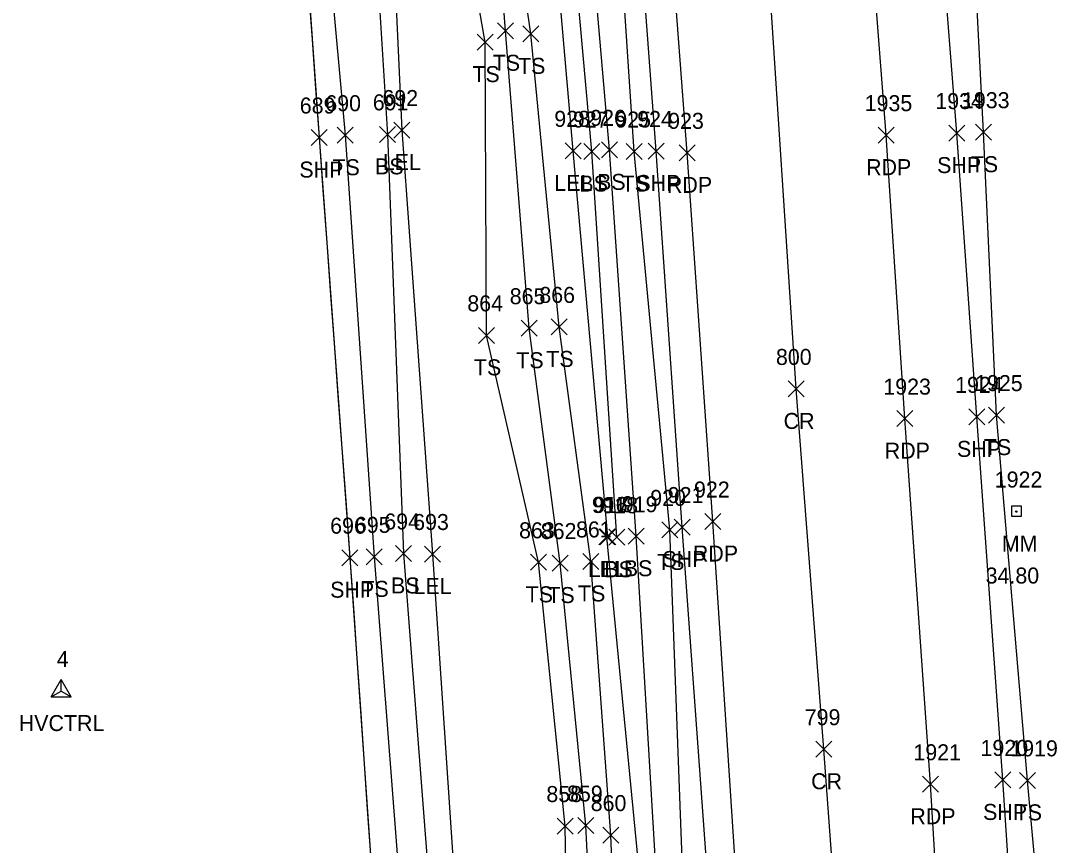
# Model space of a CAD drawing. Extents: x 1650221 to 1650634, y 244606 to 249996.
# Drawn here: x 1650342.9 to 1650471.2, y 245132.2 to 245235.3 of the extents above; entities that cross this region are included whole.
import ezdxf

# ---------------------------------------------------------------- set-up
doc = ezdxf.new("R2010")
doc.units = 0
for name, color, linetype in [('C_A', 7, 'Continuous'), ('C_I', 7, 'Continuous'), ('CPSM', 7, 'Continuous'), ('L_A', 7, 'Continuous'), ('L_I', 7, 'Continuous'), ('L_TIC', 7, 'Continuous'), ('LARO', 7, 'Continuous'), ('LELB', 7, 'Continuous'), ('LSOGP', 7, 'Continuous'), ('P_A', 7, 'Continuous'), ('P_I', 7, 'Continuous'), ('P_TIC', 7, 'Continuous'), ('PET', 7, 'Continuous'), ('PRC', 7, 'Continuous'), ('PSP', 7, 'Continuous'), ('S_A', 7, 'Continuous'), ('S_C', 7, 'Continuous'), ('S_I', 7, 'Continuous'), ('SRM', 7, 'Continuous')]:
    doc.layers.add(name, color=color, linetype=linetype)

msp = doc.modelspace()

# ---------------------------------------------------------------- linework, layer by layer
at = {"layer": 'CPSM'}
for p, q in [((1650346.74, 245150.77), (1650347.99, 245152.93)), ((1650349.24, 245150.77), (1650347.99, 245152.93)), ((1650347.99, 245151.49), (1650347.99, 245152.93)), ((1650346.74, 245150.77), (1650347.99, 245151.49)), ((1650347.99, 245151.49), (1650347.99, 245151.49)), ((1650347.99, 245151.49), (1650349.24, 245150.77)), ((1650346.74, 245150.77), (1650349.24, 245150.77))]:
    msp.add_line(p, q, dxfattribs=at)
at = {"layer": 'L_TIC'}
for points in [[(1650402.51, 245233.02), (1650404.51, 245235.02)], [(1650404.51, 245233.02), (1650402.51, 245235.02)], [(1650405.67, 245232.63), (1650407.67, 245234.63)], [(1650407.67, 245232.63), (1650405.67, 245234.63)], [(1650399.96, 245231.6), (1650401.96, 245233.6)], [(1650401.96, 245231.6), (1650399.96, 245233.6)], [(1650382.48, 245219.96), (1650384.48, 245221.96)], [(1650384.48, 245219.96), (1650382.48, 245221.96)], [(1650387.77, 245220.07), (1650389.77, 245222.07)], [(1650389.77, 245220.07), (1650387.77, 245222.07)], [(1650389.54, 245220.61), (1650391.54, 245222.61)], [(1650391.54, 245220.61), (1650389.54, 245222.61)], [(1650462.25, 245220.34), (1650464.25, 245222.34)], [(1650464.25, 245220.34), (1650462.25, 245222.34)], [(1650410.97, 245218.01), (1650412.97, 245220.01)], [(1650412.97, 245218.01), (1650410.97, 245220.01)], [(1650413.29, 245217.92), (1650415.29, 245219.92)], [(1650415.29, 245217.92), (1650413.29, 245219.92)], [(1650415.52, 245218.13), (1650417.52, 245220.13)], [(1650417.52, 245218.13), (1650415.52, 245220.13)], [(1650418.6, 245217.92), (1650420.6, 245219.92)], [(1650420.6, 245217.92), (1650418.6, 245219.92)], [(1650405.45, 245195.84), (1650407.45, 245197.84)], [(1650407.45, 245195.84), (1650405.45, 245197.84)], [(1650409.2, 245196), (1650411.2, 245198)], [(1650411.2, 245196), (1650409.2, 245198)], [(1650400.15, 245194.95), (1650402.15, 245196.95)], [(1650402.15, 245194.95), (1650400.15, 245196.95)], [(1650463.89, 245184.98), (1650465.89, 245186.98)], [(1650465.89, 245184.98), (1650463.89, 245186.98)], [(1650415.16, 245169.75), (1650417.16, 245171.75)], [(1650417.16, 245169.75), (1650415.16, 245171.75)], [(1650415.29, 245169.75), (1650417.29, 245171.75)], [(1650417.29, 245169.75), (1650415.29, 245171.75)], [(1650416.42, 245169.71), (1650418.42, 245171.71)], [(1650418.42, 245169.71), (1650416.42, 245171.71)], [(1650418.86, 245169.84), (1650420.86, 245171.84)], [(1650420.86, 245169.84), (1650418.86, 245171.84)], [(1650423.05, 245170.63), (1650425.05, 245172.63)], [(1650425.05, 245170.63), (1650423.05, 245172.63)], [(1650386.1, 245167.26), (1650388.1, 245169.26)], [(1650388.1, 245167.26), (1650386.1, 245169.26)], [(1650389.77, 245167.69), (1650391.77, 245169.69)], [(1650391.77, 245167.69), (1650389.77, 245169.69)], [(1650393.38, 245167.62), (1650395.38, 245169.62)], [(1650395.38, 245167.62), (1650393.38, 245169.62)], [(1650406.62, 245166.58), (1650408.62, 245168.58)], [(1650408.62, 245166.58), (1650406.62, 245168.58)], [(1650409.33, 245166.49), (1650411.33, 245168.49)], [(1650411.33, 245166.49), (1650409.33, 245168.49)], [(1650413.16, 245166.69), (1650415.16, 245168.69)], [(1650415.16, 245166.69), (1650413.16, 245168.69)], [(1650467.74, 245139.33), (1650469.74, 245141.33)], [(1650469.74, 245139.33), (1650467.74, 245141.33)], [(1650409.98, 245133.62), (1650411.98, 245135.62)], [(1650411.98, 245133.62), (1650409.98, 245135.62)], [(1650412.57, 245133.68), (1650414.57, 245135.68)], [(1650414.57, 245133.68), (1650412.57, 245135.68)], [(1650415.66, 245132.49), (1650417.66, 245134.49)], [(1650417.66, 245132.49), (1650415.66, 245134.49)]]:
    msp.add_lwpolyline(points, dxfattribs=at)
at = {"layer": 'LARO'}
for points in [[(1650421.38, 244936.36), (1650423.35, 244936.27), (1650425.89, 244936.22), (1650434.3, 244938.37), (1650430.48, 244972), (1650427.02, 245018.52), (1650423.68, 245067.08), (1650420.77, 245123.48), (1650416.16, 245170.75), (1650416.29, 245170.75), (1650411.97, 245219.01), (1650407.36, 245272.17), (1650403.92, 245328.57), (1650398.22, 245379.76), (1650393.14, 245434.28), (1650390.04, 245478.89), (1650387.05, 245523.12), (1650386.02, 245551.2)], [(1650370.23, 245505.43), (1650373.27, 245470.75), (1650376.08, 245419.34), (1650380.61, 245367.82), (1650383.54, 245316.3), (1650388.29, 245270.51), (1650390.54, 245221.61), (1650394.38, 245168.62), (1650397.75, 245118.3), (1650404.08, 245063.51), (1650406.12, 245018.23), (1650409.93, 244966.8), (1650411.89, 244938.28)]]:
    msp.add_lwpolyline(points, dxfattribs=at)
at = {"layer": 'LELB'}
for points in [[(1650349.13, 245703.09), (1650351.39, 245660.59), (1650355.99, 245608.05), (1650358.47, 245560.96), (1650362.91, 245508.7), (1650365.76, 245471.06), (1650369.41, 245419.53), (1650373.04, 245367.18), (1650376.89, 245316.29), (1650379.01, 245269.77), (1650383.48, 245220.96), (1650387.1, 245168.26), (1650390.97, 245118.17), (1650394.99, 245063.19), (1650398.03, 245017.1), (1650401.94, 244967.25), (1650403.81, 244936.86), (1650407.34, 244889.23), (1650410.84, 244834.73), (1650414.52, 244785.95), (1650419.34, 244732.83), (1650422.93, 244682.99), (1650426.36, 244632.18), (1650427.51, 244611.7)], [(1650355.71, 245703.22), (1650358.45, 245660.47), (1650361.92, 245609.02), (1650362.95, 245561.76), (1650366.97, 245508.68), (1650370.97, 245471.38), (1650374.07, 245419.38), (1650376.64, 245367.03), (1650382.18, 245316.08), (1650385.68, 245270.43), (1650388.77, 245221.07), (1650390.77, 245168.69), (1650394.69, 245118), (1650401.29, 245063.19), (1650403.89, 245017.69), (1650406.99, 244966.96), (1650408.31, 244937.61), (1650413.12, 244889.16), (1650416.09, 244835.73), (1650420.51, 244786.1), (1650423.8, 244733.3), (1650426.51, 244682.57), (1650434.12, 244632.73), (1650437.01, 244612.78)], [(1650458.26, 244631.23), (1650456.79, 244671.65), (1650452.78, 244720.4), (1650448.37, 244766.08), (1650444.9, 244801.26), (1650441.62, 244837.94), (1650439.87, 244879.23), (1650437.68, 244923.9), (1650433.87, 244972.21), (1650429.49, 245017.89), (1650426.15, 245066.7), (1650422.69, 245123.12), (1650419.86, 245170.84), (1650416.52, 245219.13), (1650411.95, 245271.56), (1650407.71, 245328.35), (1650401.82, 245379.92), (1650396.45, 245433.97), (1650394.84, 245478.56), (1650392.49, 245522.5), (1650389.35, 245551.29), (1650385.12, 245588.75), (1650380.77, 245632.36), (1650373.15, 245685.41)], [(1650462.3, 244631.92), (1650459.1, 244671.43), (1650455.6, 244720.68), (1650451.8, 244765.92), (1650449.21, 244801.88), (1650446.61, 244838.72), (1650443.38, 244880.99), (1650440.04, 244922.8), (1650437.91, 244972.67), (1650433.82, 245018.12), (1650431.01, 245067.65), (1650425.84, 245123.86), (1650424.05, 245171.63), (1650419.6, 245218.92), (1650416.04, 245272.16), (1650411.76, 245328.09), (1650406.63, 245381.03), (1650402.95, 245434.27), (1650400.25, 245479.81), (1650396.41, 245522.79), (1650395.43, 245551.92), (1650392.44, 245589.61), (1650388.27, 245633.5), (1650384.04, 245685.26)], [(1650471.05, 245115.28), (1650468.74, 245140.33), (1650464.89, 245185.98), (1650463.25, 245221.34), (1650461.37, 245257.85), (1650459.32, 245284.8), (1650456.97, 245315.55), (1650454.6, 245356.59), (1650452.98, 245378.54), (1650450.43, 245426.58), (1650446.12, 245463.42), (1650443.52, 245512.09), (1650441.71, 245548.12), (1650438.37, 245589.38), (1650434.29, 245631.65), (1650429.68, 245683.37)], [(1650417.42, 245170.71), (1650414.29, 245218.92), (1650409.59, 245271.3), (1650405.4, 245327.96), (1650399.15, 245380.06), (1650394.45, 245434.24), (1650392.17, 245479.25), (1650388.55, 245523.47), (1650387.04, 245550.93), (1650374.54, 245599.04)], [(1650411.56, 245100.31), (1650410.98, 245134.62), (1650407.62, 245167.58), (1650401.15, 245195.95), (1650400.96, 245232.6), (1650396.91, 245255.72), (1650396.39, 245280.59), (1650392.18, 245317.33), (1650390.56, 245355.55), (1650386.02, 245389.39), (1650383.37, 245430.51), (1650379.67, 245462.51), (1650379.96, 245467.43), (1650380, 245489.06), (1650377.56, 245510.96), (1650374.72, 245546.33), (1650373.24, 245560.96), (1650373.27, 245589.26)], [(1650417.99, 245100.65), (1650416.66, 245133.49), (1650414.16, 245167.69), (1650410.2, 245197), (1650406.67, 245233.63), (1650402.8, 245260.5), (1650403.69, 245281.19), (1650397.99, 245316.2), (1650398.84, 245356.67), (1650390.42, 245389.46), (1650390.16, 245432.43), (1650385.39, 245460.04), (1650384.98, 245466.18), (1650387.77, 245488.08), (1650384.3, 245517.36), (1650381.95, 245546.8), (1650375.57, 245561.13), (1650373.27, 245589.26)], [(1650438.88, 244749.14), (1650437.59, 244767.7), (1650432.8, 244801.89), (1650429.64, 244835.41), (1650428.64, 244877.68), (1650423.48, 244923.01), (1650423.35, 244936.27), (1650423.08, 244949.37), (1650423.3, 244968.5), (1650419.67, 244981.26), (1650420.71, 245016.76), (1650415.5, 245052.76), (1650413.6, 245072.27), (1650415.28, 245100.97), (1650413.57, 245134.68), (1650410.33, 245167.49), (1650406.45, 245196.84), (1650403.51, 245234.02), (1650401.64, 245258.7)]]:
    msp.add_lwpolyline(points, dxfattribs=at)
at = {"layer": 'LSOGP'}
msp.add_lwpolyline([(1650378.91, 245239.03), (1650379.35, 245232.91), (1650379.78, 245226.79), (1650380.21, 245220.67), (1650380.7, 245214.11), (1650381.18, 245207.54), (1650381.66, 245200.98), (1650382.14, 245194.41), (1650382.62, 245187.85), (1650383.11, 245181.29), (1650383.59, 245174.72), (1650384.07, 245168.16), (1650384.5, 245161.87), (1650384.94, 245155.58), (1650385.37, 245149.29), (1650385.81, 245143.01), (1650386.24, 245136.72), (1650386.67, 245130.43)], dxfattribs=at)
at = {"layer": 'P_TIC'}
for points in [[(1650379.21, 245219.67), (1650381.21, 245221.67)], [(1650381.21, 245219.67), (1650379.21, 245221.67)], [(1650450.1, 245219.97), (1650452.1, 245221.97)], [(1650452.1, 245219.97), (1650450.1, 245221.97)], [(1650458.93, 245220.23), (1650460.93, 245222.23)], [(1650460.93, 245220.23), (1650458.93, 245222.23)], [(1650421.33, 245217.99), (1650423.33, 245219.99)], [(1650423.33, 245217.99), (1650421.33, 245219.99)], [(1650425.2, 245217.76), (1650427.2, 245219.76)], [(1650427.2, 245217.76), (1650425.2, 245219.76)], [(1650438.84, 245188.25), (1650440.84, 245190.25)], [(1650440.84, 245188.25), (1650438.84, 245190.25)], [(1650452.42, 245184.54), (1650454.42, 245186.54)], [(1650454.42, 245184.54), (1650452.42, 245186.54)], [(1650461.4, 245184.76), (1650463.4, 245186.76)], [(1650463.4, 245184.76), (1650461.4, 245186.76)], [(1650424.59, 245170.99), (1650426.59, 245172.99)], [(1650426.59, 245170.99), (1650424.59, 245172.99)], [(1650428.44, 245171.68), (1650430.44, 245173.68)], [(1650430.44, 245171.68), (1650428.44, 245173.68)], [(1650383.07, 245167.16), (1650385.07, 245169.16)], [(1650385.07, 245167.16), (1650383.07, 245169.16)], [(1650442.28, 245143.22), (1650444.28, 245145.22)], [(1650444.28, 245143.22), (1650442.28, 245145.22)], [(1650455.62, 245138.84), (1650457.62, 245140.84)], [(1650457.62, 245138.84), (1650455.62, 245140.84)], [(1650464.66, 245139.38), (1650466.66, 245141.38)], [(1650466.66, 245139.38), (1650464.66, 245141.38)]]:
    msp.add_lwpolyline(points, dxfattribs=at)
at = {"layer": 'PET'}
for points in [[(1650468.61, 244633.66), (1650465.16, 244679.18), (1650461.18, 244730.39), (1650457.78, 244777.29), (1650455.76, 244806.01), (1650453.3, 244838.79), (1650450.33, 244880.04), (1650447.22, 244922.32), (1650443.48, 244972.73), (1650440.49, 245018.18), (1650436.73, 245069.12), (1650432.63, 245123.79), (1650429.44, 245172.68), (1650426.2, 245218.76), (1650422.12, 245272.82), (1650418.28, 245328.28), (1650414.28, 245381.59), (1650410.42, 245434.18), (1650407.03, 245480.26), (1650404.25, 245522.13), (1650401.81, 245552.98), (1650399.16, 245589.27), (1650395.97, 245634.45), (1650392.36, 245685.55)], [(1650458.15, 245114.32), (1650456.62, 245139.84), (1650453.42, 245185.54), (1650451.1, 245220.97), (1650448.32, 245256.66), (1650446.89, 245283.96), (1650444.13, 245314.19), (1650440.98, 245355.92), (1650439.55, 245378.58), (1650435.64, 245425.9), (1650433.13, 245463.89), (1650429.51, 245512.19), (1650427.14, 245547.69), (1650424.3, 245587.11), (1650421.18, 245630.65), (1650417.91, 245681.78)]]:
    msp.add_lwpolyline(points, dxfattribs=at)
at = {"layer": 'PRC'}
msp.add_lwpolyline([(1650447.57, 245085.81), (1650443.28, 245144.22), (1650439.84, 245189.25), (1650436.21, 245244.62), (1650432.57, 245294.06), (1650428.87, 245344.44), (1650424.91, 245397.45), (1650422.06, 245440.46), (1650418.2, 245485.2), (1650414.81, 245534.63), (1650412.73, 245565.5), (1650409.49, 245611.37), (1650407.05, 245649.82), (1650403.01, 245697.04)], dxfattribs=at)
at = {"layer": 'PSP'}
for points in [[(1650345.78, 245703.18), (1650348.63, 245659.65), (1650352.24, 245608.27), (1650356.14, 245560.76), (1650359.83, 245508.67), (1650362.71, 245470.35), (1650366.37, 245419.55), (1650370.09, 245366.17), (1650373.73, 245316.16), (1650376.75, 245269.64), (1650380.21, 245220.67), (1650384.07, 245168.16), (1650387.54, 245117.86), (1650391.85, 245063.26), (1650394.9, 245017.42), (1650398.56, 244967.17), (1650400.8, 244936.49), (1650404.42, 244889.02), (1650408.47, 244833.97), (1650411.77, 244786.13), (1650415.79, 244732.16), (1650419.27, 244682.87), (1650423.02, 244632.43), (1650424.78, 244611.26)], [(1650464.84, 244632.07), (1650461.81, 244671.31), (1650457.94, 244720.75), (1650454.77, 244765.54), (1650451.99, 244802.46), (1650449.34, 244838.71), (1650446.5, 244879.72), (1650443.46, 244922.98), (1650439.98, 244973.19), (1650436.37, 245018.02), (1650433.26, 245068.28), (1650429.09, 245123.84), (1650425.59, 245171.99), (1650422.33, 245218.99), (1650418.38, 245272.19), (1650414.3, 245328), (1650410.4, 245381.3), (1650406.52, 245434.23), (1650403.48, 245480), (1650400.24, 245522.79), (1650398.25, 245552.46), (1650395.41, 245589.43), (1650392.23, 245633.8), (1650388.44, 245685.1)], [(1650467.35, 245115.19), (1650465.66, 245140.38), (1650462.4, 245185.76), (1650459.93, 245221.23), (1650457.1, 245257.2), (1650455.22, 245284.62), (1650453.41, 245314.94), (1650449.96, 245356.27), (1650448.46, 245377.97), (1650444.62, 245426.85), (1650442.19, 245463.43), (1650438.55, 245512.23), (1650436.23, 245548.05), (1650433.37, 245588.35), (1650430.25, 245631.19), (1650426.21, 245683.01)]]:
    msp.add_lwpolyline(points, dxfattribs=at)
at = {"layer": 'SRM'}
for p, q in [((1650468, 245174.59), (1650466.75, 245174.59)), ((1650466.75, 245174.59), (1650466.75, 245173.34)), ((1650468, 245174.59), (1650466.75, 245174.59)), ((1650466.75, 245174.59), (1650466.75, 245173.34)), ((1650468, 245173.34), (1650468, 245174.59)), ((1650468, 245173.34), (1650468, 245174.59)), ((1650466.75, 245173.34), (1650468, 245173.34)), ((1650466.75, 245173.34), (1650468, 245173.34))]:
    msp.add_line(p, q, dxfattribs=at)
msp.add_circle((1650467.35, 245173.92), 0.0833, dxfattribs=at)

# ---------------------------------------------------------------- texts
at = {"layer": 'C_A'}
msp.add_text('HVCTRL', height=2, dxfattribs=at).set_placement((1650342.68, 245146.49))
at = {"layer": 'C_I'}
msp.add_text('4', height=2, dxfattribs=at).set_placement((1650347.42, 245154.49))
at = {"layer": 'L_A'}
for s, p in [('TS', (1650401.92, 245229.02)), ('TS', (1650405.08, 245228.63)), ('TS', (1650399.37, 245227.6)), ('TS', (1650381.89, 245215.96)), ('BS', (1650387.21, 245216.07)), ('LEL', (1650388.18, 245216.61)), ('TS', (1650461.66, 245216.34)), ('LEL', (1650409.61, 245214.01)), ('BS', (1650412.74, 245213.92)), ('BS', (1650414.96, 245214.13)), ('TS', (1650418.01, 245213.92)), ('TS', (1650404.86, 245191.84)), ('TS', (1650408.61, 245192)), ('TS', (1650399.56, 245190.95)), ('TS', (1650463.3, 245180.98)), ('LEL', (1650413.8, 245165.75)), ('LEL', (1650413.93, 245165.75)), ('BS', (1650415.86, 245165.71)), ('BS', (1650418.3, 245165.84)), ('TS', (1650422.46, 245166.63)), ('TS', (1650385.5, 245163.26)), ('BS', (1650389.21, 245163.69)), ('LEL', (1650392.02, 245163.62)), ('TS', (1650406.03, 245162.58)), ('TS', (1650408.74, 245162.49)), ('TS', (1650412.57, 245162.69)), ('TS', (1650467.15, 245135.33))]:
    msp.add_text(s, height=2, dxfattribs=at).set_placement(p)
at = {"layer": 'L_I'}
for s, p in [('692', (1650388.13, 245224.61)), ('690', (1650380.99, 245223.96)), ('691', (1650386.93, 245224.07)), ('1933', (1650460.56, 245224.34)), ('926', (1650414.1, 245222.13)), ('928', (1650409.61, 245222.01)), ('927', (1650411.93, 245221.92)), ('925', (1650417.24, 245221.92)), ('864', (1650398.74, 245198.95)), ('865', (1650404.04, 245199.84)), ('866', (1650407.74, 245200)), ('1925', (1650462.2, 245188.98)), ('920', (1650421.6, 245174.63)), ('916', (1650414.31, 245173.75)), ('917', (1650414.49, 245173.75)), ('918', (1650415.62, 245173.71)), ('919', (1650418.05, 245173.84)), ('695', (1650384.69, 245171.26)), ('694', (1650388.36, 245171.69)), ('693', (1650391.97, 245171.62)), ('863', (1650405.21, 245170.58)), ('862', (1650407.92, 245170.49)), ('861', (1650412.32, 245170.69)), ('1919', (1650466.6, 245143.33)), ('858', (1650408.62, 245137.62)), ('859', (1650411.2, 245137.68)), ('860', (1650414.16, 245136.49))]:
    msp.add_text(s, height=2, dxfattribs=at).set_placement(p)
at = {"layer": 'P_A'}
for s, p in [('SHP', (1650377.75, 245215.67)), ('RDP', (1650448.58, 245215.97)), ('SHP', (1650457.46, 245216.23)), ('SHP', (1650419.87, 245213.99)), ('RDP', (1650423.69, 245213.76)), ('CR', (1650438.27, 245184.25)), ('RDP', (1650450.91, 245180.54)), ('SHP', (1650459.94, 245180.76)), ('SHP', (1650423.12, 245166.99)), ('RDP', (1650426.93, 245167.68)), ('SHP', (1650381.6, 245163.16)), ('CR', (1650441.71, 245139.22)), ('RDP', (1650454.11, 245134.84)), ('SHP', (1650463.2, 245135.38))]:
    msp.add_text(s, height=2, dxfattribs=at).set_placement(p)
at = {"layer": 'P_I'}
for s, p in [('689', (1650377.8, 245223.67)), ('1935', (1650448.4, 245223.97)), ('1934', (1650457.23, 245224.23)), ('924', (1650419.97, 245221.99)), ('923', (1650423.84, 245221.76)), ('800', (1650437.31, 245192.25)), ('1924', (1650459.71, 245188.76)), ('1923', (1650450.73, 245188.54)), ('921', (1650423.79, 245174.99)), ('922', (1650427.07, 245175.68)), ('696', (1650381.6, 245171.16)), ('799', (1650440.91, 245147.22)), ('1921', (1650454.49, 245142.84)), ('1920', (1650462.88, 245143.38))]:
    msp.add_text(s, height=2, dxfattribs=at).set_placement(p)
at = {"layer": 'S_A'}
msp.add_text('MM', height=2, dxfattribs=at).set_placement((1650465.54, 245168.93))
at = {"layer": 'S_C'}
msp.add_text('34.80', height=2, dxfattribs=at).set_placement((1650463.52, 245164.93))
at = {"layer": 'S_I'}
msp.add_text('1922', height=2, dxfattribs=at).set_placement((1650464.66, 245176.93))

doc.saveas('drawing.dxf')
